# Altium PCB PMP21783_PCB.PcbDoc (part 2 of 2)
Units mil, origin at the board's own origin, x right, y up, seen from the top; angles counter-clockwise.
Board outline 4600 x 4035 mil, 2 copper layers (Top Layer, Bottom Layer), stack 62 mil thick; 142 components, 69 nets, 309 pads, 93 vias.
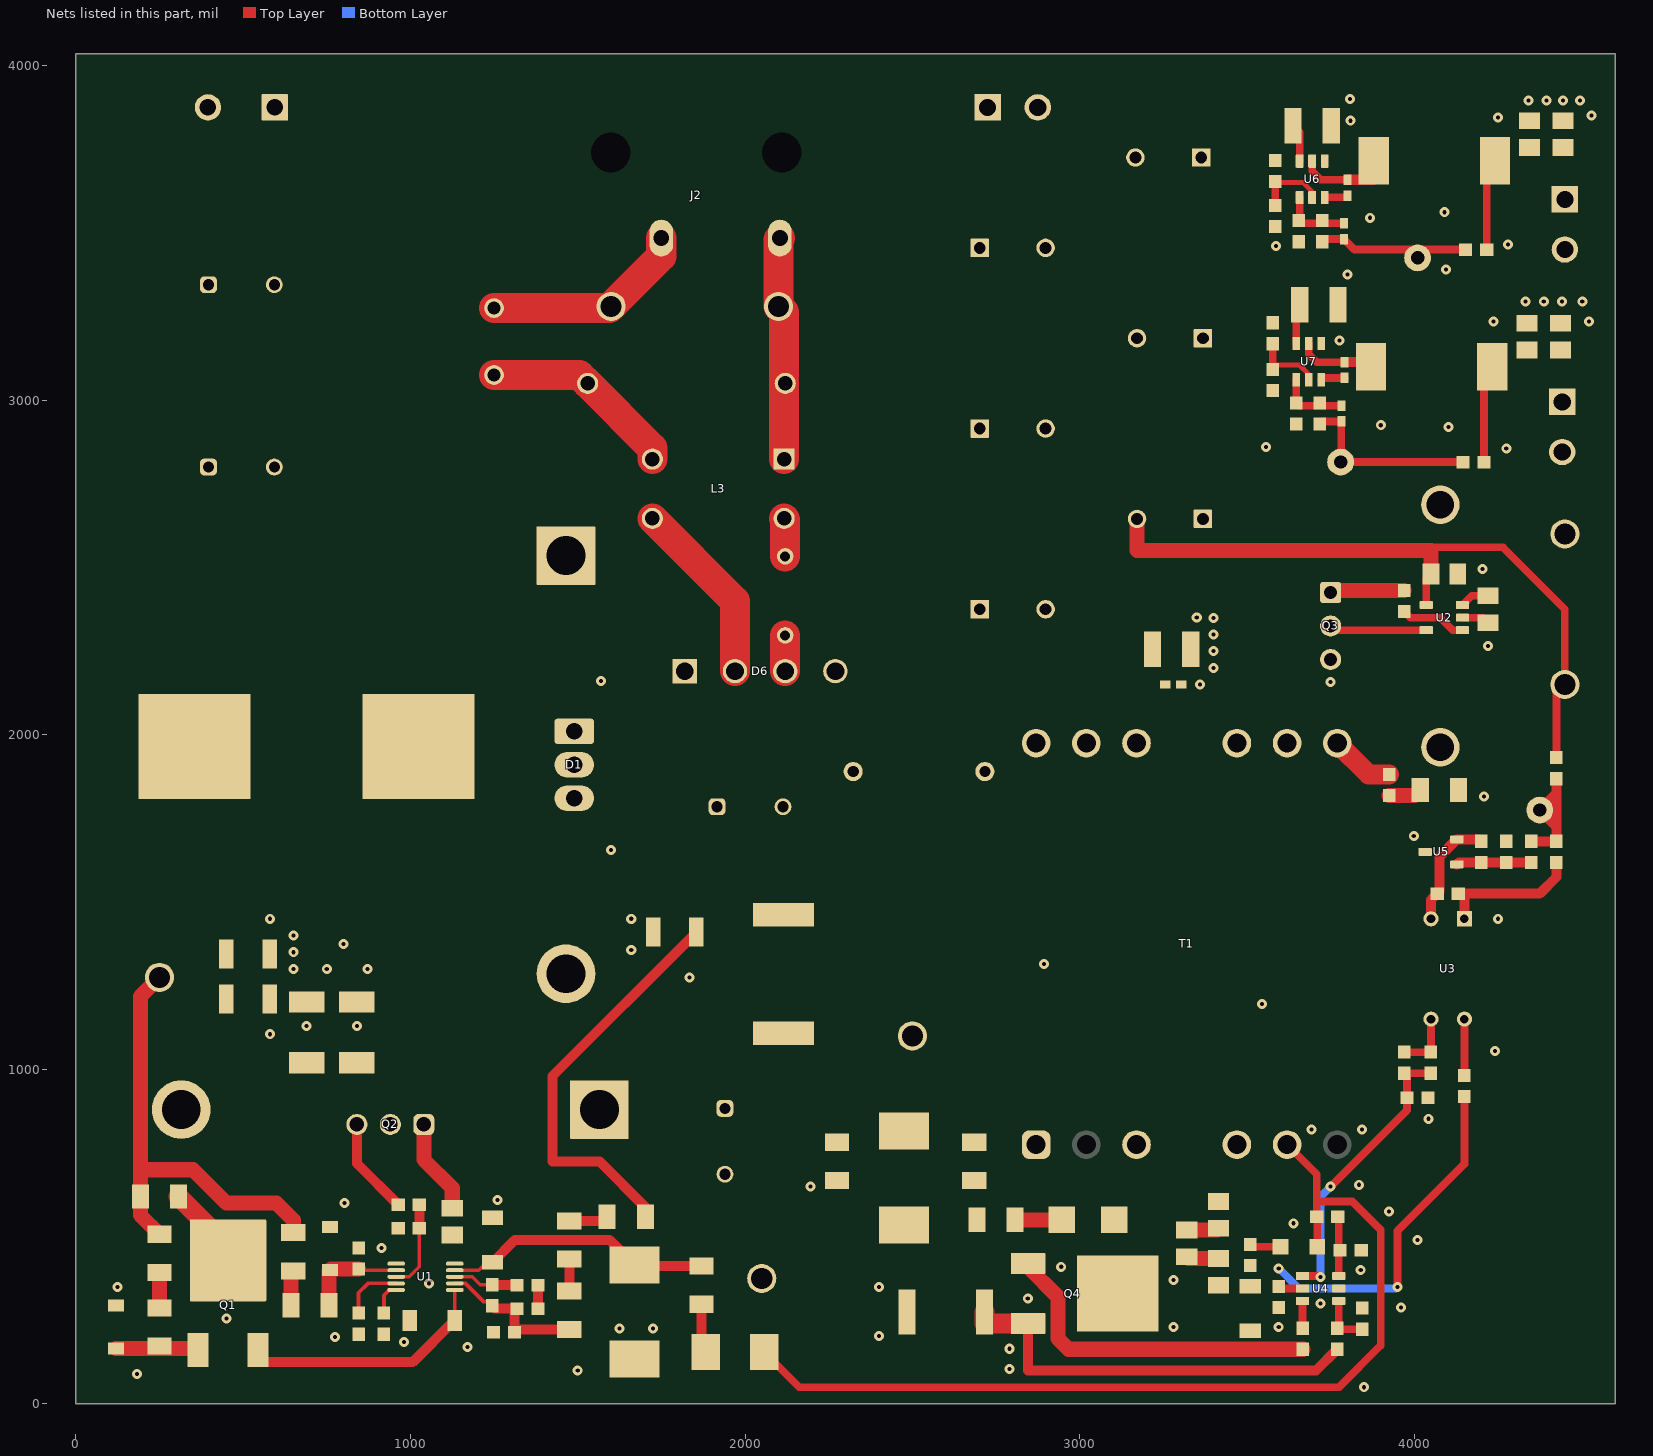
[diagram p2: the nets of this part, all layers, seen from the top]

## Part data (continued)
J3 J4 J5: library part CMP-0054822-2, "Terminal Block, 2x1, 3.81mm, 24-16 AWG, 10A, 300VAC, TH", Manufacturer="Wurth Elektronik"
L1: library part CMP-0085391-1, "Inductor, Shielded, Mn-Zn, 220 µH, 5.3 A, 0.040095 ohm, SMD", Manufacturer="Wurth Elektronik", Value1="0.040095 ohm", Value2=5.3A, ValueDisplayed=220µH
L2: library part CMP-0064437-2, "Inductor, Shielded Drum Core, Ferrite, 22 uH, 1.8 A, 0.11 ohm, SMD", Manufacturer="Wurth Elektronik", Supplier Part Number 1=732-1062-1-ND, Value1="0.11 ohm", Value2=1.8A, ValueDisplayed=22uH
L3: library part CMP-0076875-1, "Coupled inductor, 5 mH, 1.3 A, 0.2 ohm, TH", Manufacturer="Wurth Elektronik", Supplier Part Number 1=732-5576-ND, ValueDisplayed=5mH
L4: library part CMP-0064732-2, "Inductor, Toroid, Powdered Iron, 140 uH, 1 A, 0.11 ohm, TH", Manufacturer="Wurth Elektronik", Value1="0.11 ohm", Value2=1A, ValueDisplayed=140uH
L5 L6: library part CMP-0064006-1, "Inductor, Shielded Drum Core, Ferrite, 10 uH, 8 A, 0.0207 ohm, SMD", Manufacturer="Wurth Elektronik", Supplier Part Number 1=732-2158-1-ND, Value1="0.0207 ohm", Value2=8A, ValueDisplayed=10uH
LN: library part CMP-0055157-1, "Test Point, Multipurpose, Brown, TH", Color=Brown, Manufacturer=Keystone, Supplier Part Number 1=36-5125-ND
Logo1 LOGO6: library part CMP-0074837-1, "IEC 61010-1 Hot Surface Warning"
Logo2 LOGO5: library part CMP-0074835-1, "IEC 61010-1 High Voltage Warning"
Logo3: library part CMP-0074769-1
Logo4: library part CMP-0074847-1, "FCC_disclaimer"
NEU: library part CMP-0055156-1, "Test Point, Multipurpose, Blue, TH", Color=Blue, Manufacturer=Keystone, Supplier Part Number 1=36-5127-ND
Q1: library part CMP-0001119-4, "MOSFET, N-CH, 500 V, 2.8 A, DPAK", Alternate Manufacturer=None, Manufacturer=AOS, Supplier Part Number 1=785-1175-1-ND, Value2="6.7 nC"
Q2: library part CMP-0085354-1, "MOSFET, N-CH, 300 V, 44 A, TO-220-3", Alternate Manufacturer=None, Manufacturer="Infineon Technologies", Value1="? ohm", Value2="65 nC"
Q3: library part CMP-0000955-1, "MOSFET, N-CH, 100 V, 100 A, KCS0003B (TO-220-3)", Alternate Manufacturer=None, Manufacturer="Texas Instruments", Supplier Part Number 1=296-37480-5-ND, Value2="38 nC"
Q4: library part CMP-0081521-2, "MOSFET, N-CH, 700 V, 12.5 A, DPAK", Alternate Manufacturer=None, Manufacturer="Infineon Technologies", Supplier Part Number 1=IPD70R360P7SAUMA1CT-ND, Value1="? ohm", Value2="16.4 nC"
R1 R4: library part CMP-0018610-3, "RES, 1.0 M, 5%, 0.25 W, AEC-Q200 Grade 0, 1206", Manufacturer=Vishay-Dale, Power_W=250mW, Supplier Part Number 1=541-1.0MECT-ND, TempCo="200 ppm/C", Tolerance_%=5%, Value2=0.25W, Value_Code=1M00, ValueDisplayed=1.0M
R2 R5: library part CMP-0018574-3, "RES, 100 k, 5%, 0.25 W, AEC-Q200 Grade 0, 1206", Manufacturer=Vishay-Dale, Power_W=250mW, Supplier Part Number 1=541-100KECT-ND, TempCo="200 ppm/C", Tolerance_%=5%, Value2=0.25W, Value_Code=100k
R3: library part CMP-0016705-3, "RES, 1.54 k, 1%, 0.25 W, AEC-Q200 Grade 0, 1206", Manufacturer=Vishay-Dale, Power_W=250mW, Supplier Part Number 1=541-1.54KFCT-ND, TempCo="100 ppm/C", Tolerance_%=1%, Value2=0.25W, Value_Code=1k54, ValueDisplayed=1.54k
R6: library part CMP-0018242-2, "RES, 390, 1%, 0.25 W, 1206", Manufacturer="Yageo America", Power_W=250mW, Supplier Part Number 1=311-390FRCT-ND, TempCo="100 ppm/C", Tolerance_%=1%, Value2=0.25W, Value_Code=390R, ValueDisplayed=390
R7: library part CMP-0020802-2, "RES, 0, 5%, 0.125 W, 0805", Manufacturer=Rohm, Power_W=125mW, Supplier Part Number 1=RHM0.0ARCT-ND, TempCo="400 ppm/C", Tolerance_%=5%, Value2=0.125W, Value_Code=0000, ValueDisplayed=0
R8: library part CMP-0018328-2, "RES, 49.9, 1%, 0.25 W, 1206", Manufacturer="Yageo America", Power_W=250mW, Supplier Part Number 1=311-49.9FRCT-ND, TempCo="100 ppm/C", Tolerance_%=1%, Value2=0.25W, Value_Code=49R9, ValueDisplayed=49.9
R9 R30: library part CMP-0022109-5, "RES, 1.00 k, 1%, 0.1 W, AEC-Q200 Grade 0, 0603", Manufacturer=Vishay-Dale, Power_W=100mW, Supplier Part Number 1=541-1.00KHCT-ND, TempCo="100 ppm/C", Tolerance_%=1%, Value2=0.1W, Value_Code=1k00, ValueDisplayed=1.00k
R10 R11: library part CMP-0016513-2, "RES, 0.15, 1%, 1 W, 2010", Manufacturer="Stackpole Electronics Inc", Power_W=1W, Supplier Part Number 1=CSR2010FTR150CT-ND, TempCo="100 ppm/C", Tolerance_%=1%, Value_Code=R150, ValueDisplayed=0.15
R12 R15: library part CMP-0017074-3, "RES, 590 k, 1%, 0.25 W, AEC-Q200 Grade 0, 1206", Manufacturer=Vishay-Dale, Power_W=250mW, Supplier Part Number 1=541-590KFCT-ND, TempCo="100 ppm/C", Tolerance_%=1%, Value2=0.25W, Value_Code=590k
R13: library part CMP-0022010-4, "RES, 113 k, 1%, 0.1 W, AEC-Q200 Grade 0, 0603", Manufacturer=Vishay-Dale, Power_W=100mW, Supplier Part Number 1=541-113KHCT-ND, TempCo="100 ppm/C", Tolerance_%=1%, Value2=0.1W, Value_Code=113k
R14: library part CMP-0022628-4, "RES, 86.6 k, 1%, 0.1 W, AEC-Q200 Grade 0, 0603", Manufacturer=Vishay-Dale, Power_W=100mW, Supplier Part Number 1=541-86.6KHCT-ND, TempCo="100 ppm/C", Tolerance_%=1%, Value2=0.1W, Value_Code=86k6, ValueDisplayed=86.6k
R16: library part CMP-0021998-4, "RES, 10.0 k, 1%, 0.1 W, AEC-Q200 Grade 0, 0603", Manufacturer=Vishay-Dale, Power_W=100mW, Supplier Part Number 1=541-10.0KHCT-ND, TempCo="100 ppm/C", Tolerance_%=1%, Value2=0.1W, Value_Code=10k0, ValueDisplayed=10.0k
R17: library part CMP-0022204-4, "RES, 20.0 k, 1%, 0.1 W, AEC-Q200 Grade 0, 0603", Manufacturer=Vishay-Dale, Power_W=100mW, Supplier Part Number 1=541-20.0KHCT-ND, TempCo="100 ppm/C", Tolerance_%=1%, Value2=0.1W, Value_Code=20k0, ValueDisplayed=20.0k
R18 R19 R22: library part CMP-0021616-2, "RES, 2.00 M, 1%, 0.125 W, AEC-Q200 Grade 0, 0805", Manufacturer=Panasonic, Power_W=125mW, Supplier Part Number 1=P2.00MCCT-ND, TempCo="100 ppm/C", Tolerance_%=1%, Value2=0.125W, Value_Code=2M00, ValueDisplayed=2.00M
R20 R24: library part CMP-0018573-3, "RES, 0, 5%, 0.25 W, AEC-Q200 Grade 0, 1206", Manufacturer=Vishay-Dale, Power_W=250mW, Supplier Part Number 1=541-0.0ECT-ND, TempCo="200 ppm/C", Tolerance_%=5%, Value2=0.25W, Value_Code=0000, ValueDisplayed=0
R21 R27 R29: library part CMP-0025697-4, "RES, 0, 5%, 0.1 W, AEC-Q200 Grade 0, 0603", Manufacturer=Vishay-Dale, Power_W=100mW, Supplier Part Number 1=541-0.0GCT-ND, TempCo="200 ppm/C", Tolerance_%=5%, Value2=0.1W, Value_Code=0000, ValueDisplayed=0
R23 R42 R43: library part CMP-0022448-4, "RES, 49.9, 1%, 0.1 W, AEC-Q200 Grade 0, 0603", Manufacturer=Vishay-Dale, Power_W=100mW, Supplier Part Number 1=541-49.9HCT-ND, TempCo="100 ppm/C", Tolerance_%=1%, Value2=0.1W, Value_Code=49R9, ValueDisplayed=49.9
R25: library part CMP-0025743-4, "RES, 1.0, 5%, 0.1 W, AEC-Q200 Grade 0, 0603", Manufacturer=Vishay-Dale, Power_W=100mW, Supplier Part Number 1=541-1.0GCT-ND, TempCo="200 ppm/C", Tolerance_%=5%, Value2=0.1W, Value_Code=1R00, ValueDisplayed=1.0
R26: library part CMP-0022269-4, "RES, 2.05 k, 1%, 0.1 W, AEC-Q200 Grade 0, 0603", Manufacturer=Vishay-Dale, Power_W=100mW, Supplier Part Number 1=541-2.05KHCT-ND, TempCo="100 ppm/C", Tolerance_%=1%, Value2=0.1W, Value_Code=2k05, ValueDisplayed=2.05k
R28: library part CMP-0022659-4, "RES, 95.3 k, 1%, 0.1 W, AEC-Q200 Grade 0, 0603", Manufacturer=Vishay-Dale, Power_W=100mW, Supplier Part Number 1=541-95.3KHCT-ND, TempCo="100 ppm/C", Tolerance_%=1%, Value2=0.1W, Value_Code=95k3, ValueDisplayed=95.3k
R31: library part CMP-0021996-4, "RES, 107 k, 1%, 0.1 W, AEC-Q200 Grade 0, 0603", Manufacturer=Vishay-Dale, Power_W=100mW, Supplier Part Number 1=541-107KHCT-ND, TempCo="100 ppm/C", Tolerance_%=1%, Value2=0.1W, Value_Code=107k
R32: library part CMP-0022334-4, "RES, 32.4 k, 1%, 0.1 W, AEC-Q200 Grade 0, 0603", Manufacturer=Vishay-Dale, Power_W=100mW, Supplier Part Number 1=541-32.4KHCT-ND, TempCo="100 ppm/C", Tolerance_%=1%, Value2=0.1W, Value_Code=32k4, ValueDisplayed=32.4k
R33: library part CMP-0022125-4, "RES, 1.47 k, 1%, 0.1 W, AEC-Q200 Grade 0, 0603", Manufacturer=Vishay-Dale, Power_W=100mW, Supplier Part Number 1=541-1.47KHCT-ND, TempCo="100 ppm/C", Tolerance_%=1%, Value2=0.1W, Value_Code=1k47, ValueDisplayed=1.47k
R34 R47: library part CMP-0022220-4, "RES, 22.1 k, 1%, 0.1 W, AEC-Q200 Grade 0, 0603", Manufacturer=Vishay-Dale, Power_W=100mW, Supplier Part Number 1=541-22.1KHCT-ND, TempCo="100 ppm/C", Tolerance_%=1%, Value2=0.1W, Value_Code=22k1, ValueDisplayed=22.1k
R35: library part CMP-0015783-2, "RES, 0.25, 1%, 2 W, 2512", Manufacturer="Stackpole Electronics Inc", Power_W=2W, Supplier Part Number 1=CSRN2512FKR250CT-ND, TempCo="200 ppm/C", Tolerance_%=1%, Value_Code=R250, ValueDisplayed=0.25
R36: library part CMP-0022449-4, "RES, 4.02 k, 1%, 0.1 W, AEC-Q200 Grade 0, 0603", Manufacturer=Vishay-Dale, Power_W=100mW, Supplier Part Number 1=541-4.02KHCT-ND, TempCo="100 ppm/C", Tolerance_%=1%, Value2=0.1W, Value_Code=4k02, ValueDisplayed=4.02k
R37: library part CMP-0022016-4, "RES, 11.0 k, 1%, 0.1 W, AEC-Q200 Grade 0, 0603", Manufacturer=Vishay-Dale, Power_W=100mW, Supplier Part Number 1=541-11.0KHCT-ND, TempCo="100 ppm/C", Tolerance_%=1%, Value2=0.1W, Value_Code=11k0, ValueDisplayed=11.0k
R38 R39: library part CMP-0022480-4, "RES, 511 k, 1%, 0.1 W, AEC-Q200 Grade 0, 0603", Manufacturer=Vishay-Dale, Power_W=100mW, Supplier Part Number 1=541-511KHCT-ND, TempCo="100 ppm/C", Tolerance_%=1%, Value2=0.1W, Value_Code=511k
R40 R41: library part CMP-0021994-4, "RES, 105 k, 1%, 0.1 W, AEC-Q200 Grade 0, 0603", Manufacturer=Vishay-Dale, Power_W=100mW, Supplier Part Number 1=541-105KHCT-ND, TempCo="100 ppm/C", Tolerance_%=1%, Value2=0.1W, Value_Code=105k
R44 R45: library part CMP-0021990-4, "RES, 100 k, 1%, 0.1 W, AEC-Q200 Grade 0, 0603", Manufacturer=Vishay-Dale, Power_W=100mW, Supplier Part Number 1=541-100KHCT-ND, TempCo="100 ppm/C", Tolerance_%=1%, Value2=0.1W, Value_Code=100k
R46: library part CMP-0022043-4, "RES, 13.3 k, 1%, 0.1 W, AEC-Q200 Grade 0, 0603", Manufacturer=Vishay-Dale, Power_W=100mW, Supplier Part Number 1=541-13.3KHCT-ND, TempCo="100 ppm/C", Tolerance_%=1%, Value2=0.1W, Value_Code=13k3, ValueDisplayed=13.3k
T1: library part CMP-0085998-1, "Transformer, 150 uH, TH", Manufacturer="Renco Electronics", ValueDisplayed=150µH
TP1 TP2 TP3: library part CMP-0055147-1, "Test Point, Multipurpose, Red, TH", Color=Red, Manufacturer=Keystone, Supplier Part Number 1=36-5010-ND
TP4 TP7 TP8: library part CMP-0055139-1, "Test Point, Miniature, White, TH", Color=White, Manufacturer=Keystone, Supplier Part Number 1=36-5002-ND
TP5 TP6: library part CMP-0055148-1, "Test Point, Multipurpose, Black, TH", Color=Black, Manufacturer=Keystone, Supplier Part Number 1=36-5011-ND
U1: library part CMP-0073090-1, "60V Low Side Controller for Boost and SEPIC, 10-pin MSOP", Manufacturer="Texas Instruments", PackageTopMarking=ZXTT*5022, PowerWise=Y
U2: library part CMP-0013050-3, "High-Frequency Multi-Mode Synchronous Rectifier Controller, DBV0005A (SOT-23-5)", Alternate Manufacturer="Texas Instruments", Alternate PartNumber=UCC24612-1DBVT
U3: library part CMP-0006187-3, "Optocoupler, 5.3 kV, 50-600% CTR, TH", Manufacturer=Vishay-Semiconductor, Supplier Part Number 1=VO618A-ND-3, Voltage_Isolation_Vrms=5.3kV
U4: library part CMP-0078369-2, "High-Efficiency Low-Cost Flyback Controller with Secondary-Side Regulation, DBV0006A (SOT-23-6)", Alternate Manufacturer="Texas Instruments"
U5: library part CMP-0033139-1, "Low-Voltage Adjustable Precision Shunt Regulator, 80 mA, -40 to 125 degC, 3-pin SOT-23 (DBZ), Green (RoHS & no Sb/Br)", Manufacturer="Texas Instruments", Rating=Catalog, Temp Coeff(Max)(ppm/ degree C)=129
U6 U7: library part CMP-0073977-2, "4.5-V to 28-V Input, 3-A Output, EMI Friendly Synchronous Step-Down Converter, DDC0006A (SOT-23-T-6)", Alternate Manufacturer="Texas Instruments", Alternate PartNumber=TPS54302DDCT

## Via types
v1: diameter 29.92, hole 12.2, Top Layer to Bottom Layer, 89 vias
v2: diameter 29.92, hole 12.2, Top Layer to Bottom Layer, tented both sides, 4 vias

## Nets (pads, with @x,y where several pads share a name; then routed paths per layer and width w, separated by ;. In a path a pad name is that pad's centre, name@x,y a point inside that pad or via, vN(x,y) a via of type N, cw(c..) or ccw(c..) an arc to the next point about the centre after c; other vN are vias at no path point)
12V: C14.2 C15.2 C16.2 C17.2 C18.2 C19.2 C20.1 C21.1 C27.1 C36.1 C37.1 J3.2 R23.2 R38.2 R39.2 T1.10 T1.11 T1.12 TP2.1 U2.4 U6.3 U7.3 | length 2306.8
  Top Layer w23: C36.1@3637.91,3820 3657.6,3800.31 U6.3@3657.6,3714.13 ; U7.3@3647.25,3169.04 3647.25,3274.33 C37.1@3657.91,3285 ; U2.4@4035.87,2387.4 4035.87,2465.87 C27.1@4050,2480 ; 4050,2560 4265,2560 4450,2375 TP2.1@4450,2150 4425,2125 R23.2@4425,1931.5
  Top Layer w45: C19.2@3171.57,2645 3171.57,2550 4050,2550 C27.1@4050,2480
AUX: D2.2 D9.2 R31.2 T1.5 | length 2852.3
  Top Layer w23: D2.2@2057.01,155 2162.01,50 3775,50 3900,175 3900,520 3815,605 3708.51,605 ; T1.5@3620,775 3708.51,686.5 3708.51,605 ; D9.2@3710.12,470 3710.12,558.39 R31.2@3708.51,560 3708.51,605
FB_U1: C11.1 C12.1 R15.1 R16.2 U1.2 | length 456.8
  Top Layer w11: U1.2@1132.6,360.31 1164.69,360.31 1220,305 1233.5,305 C11.1@1245,293.5
  Top Layer w30: C11.1@1245,293.5 1253.5,285 C12.1@1318.5,285 1311.5,277.99 R16.2@1311.5,215 1319.41,222.91 R15.1@1475,222.91
FB_U4: C30.2 R32.1 R36.2 U4.1 | length 854.2
  Top Layer w23: U4.1@3665.87,382.4 3717.6,382.4 v1(3720,380) ; v1(3750,650) 3978.5,878.51 R36.2@3978.5,915 3978.5,980 C30.2@3970,988.5 R32.1@4050,988.5
  Bottom Layer w23: v1(3720,380) 3720,620 v1(3750,650)
FB_U6: C42.2 R44.1 R46.2 U6.4 | length 208.7
  Top Layer w23: U6.4@3657.6,3605.86 3657.6,3539.09 R46.2@3655,3536.49 3662.87,3528.62 C42.2@3790,3528.62
FB_U7: C43.2 R45.1 R47.2 U7.4 | length 207.7
  Top Layer w23: U7.4@3647.25,3060.78 3647.25,2991.53 R47.2@3647.12,2991.41 3655,2983.53 C43.2@3782.12,2983.53
GND: C1.2 C2.2 C3.2 C4.2 C5.2 C6.2 C7.2 C8.2 C9.2 C10.2 C22.2 C23.2 C28.2 C29.1 C32.2 C33.2 D3.2 D4.2 D5.2 D6.4 H1.1 H1.2 H2.1 H2.2 J1.1 R10.1 R11.1 R13.1 R14.1 R16.1 R34.1 R35.1 R36.1 T1.4 TP5.1 U1.6 U4.5
  other v1: 3850,50 183.07,89.53 1500,100 2790,105 2790,165 1170,170 981.08,185 775,200 2400,202.89 1625,225 1725,225 3280,230 3595,230 450,255 3960,288.33 2845,315 125,350 2400,350 1055,360 3280,370 3840,400 2945,410 914.03,466.5 4009.19,490 3639.12,540 3925,575 802.5,600.31 1260,610 2195.91,650 3835,655 3692.48,820.16 3843.5,820.16 4042,852.3 4241.1,1055 580,1105 690,1130 840,1130 3545,1195 1834.57,1275 650,1300 750,1300 872.27,1300 2894,1315 650,1350 1660,1357.27 800,1375 650,1400 580,1450 1660,1450 1600,1655 1569.54,2160
  other v2: 3720,300
NetC1_1: C1.1 C2.1 C3.1 C4.1 J1.2 L1.1 R1.1 R2.2 R3.2 TP1.1 | length 1372.3
  Top Layer w45: R2.2@250,507.09 192.91,564.17 R3.2@192.91,620 192.91,700 ; TP1.1@250,1275 192.91,1217.91 192.91,700 ; R1.1@650,512.09 650,550 600,600 450,600 350,700 192.91,700
NetC5_1: C5.1 C6.1 D1.2 D6.1 L2.1 R8.2 | length 1224.9
  Top Layer w30: R8.2@1702.09,560 1702.09,587.91 1565,725 1425,725 1425,980.04 C6.1@1854.96,1410
NetC7_1: C7.1 Q1.3 U1.1 | length 766
  Top Layer w11: C7.1@1131.93,250 1132.6,250.67 U1.1@1132.6,340.63
  Top Layer w30: Q1.3@544.76,161.14 544.76,125 1006.93,125 C7.1@1131.93,250
NetC8_1: C8.1 D3.1 R6.2 U1.4 | length 807.1
  Top Layer w11: U1.4@1132.6,399.68 1204.19,399.68 1227.58,423.07 C8.1@1245,423.07
  Top Layer w30: C8.1@1245,423.07 1311.93,490 1595.49,490 D3.1@1670,415.49 1673.41,412.09 R6.2@1870,412.09
NetC9_1: C9.1 R9.1 U1.8 | length 266.5
  Top Layer w11: U1.8@957.4,380 996.5,380 1026.5,410 C9.1@1026.5,525
  Top Layer w30: C9.1@1026.5,525 R9.1@1026.5,595
NetC10_1: C10.1 U1.10 | length 96.8
  Top Layer w11: C10.1@920,271.5 920.98,272.48 920.98,325 936.61,340.63 U1.10@957.4,340.63
NetC11_2: C11.2 R17.1 U1.3 | length 196.3
  Top Layer w11: U1.3@1132.6,380 1185,380 1208.5,356.5 C11.2@1245,356.5
  Top Layer w30: C11.2@1245,356.5 1246.5,355 R17.1@1318.5,355
NetC12_2: C12.2 R17.2 | length 70
  Top Layer w30: C12.2@1381.5,285 R17.2@1381.5,355
NetC13_1: C13.1 F1.1 L3.2 | length 596.6
  Top Layer w90: F1.1@1250,3075 1504.72,3075 C13.1@1529.72,3050 1723.15,2856.57 L3.2@1723.15,2823.58
NetC13_2: C13.2 J2.1 L3.1 NEU.1 | length 669.2
  Top Layer w90: J2.1@2104.09,3484.09 2100,3480 NEU.1@2100,3280 2116.85,3263.15 L3.1@2116.85,2823.58
NetC24_2: C24.2 D7.1 R20.2
NetC25_1: C25.1 R24.2 | length 99.7
  Top Layer w45: C25.1@3925,1818.5 4001.42,1818.5 R24.2@4017.91,1835
NetC25_2: C25.2 Q3.2 T1.7 T1.8 T1.9 U2.5 | length 484.7
  Top Layer w23: Q3.2@3750,2325 3762.4,2312.6 U2.5@4035.87,2312.6
  Top Layer w60: T1.7@3770,1975 3863.51,1881.5 C25.2@3925,1881.5
NetC26_1: C26.1 U2.3 | length 87.3
  Top Layer w23: U2.3@4144.13,2387.4 4171.74,2415 C26.1@4220,2415
NetC28_1: C28.1 C29.2 R22.1 R25.2 R27.2 U4.2 | length 1106.8
  Top Layer w23: C29.2@3595,351.5 3601.5,345 U4.2@3665.87,345 ; v1(3950,350) 3950,517.09 4150,717.09 R27.2@4150,918.5
  Bottom Layer w23: v2(3595,405) 3655.01,345 3945,345 v1(3950,350)
NetC30_1: C30.1 R32.2 U3.3 | length 178.5
  Top Layer w23: C30.1@3970,1051.5 R32.2@4050,1051.5 U3.3@4050,1150
NetC31_1: C31.1 R28.1 R37.2 U5.1 | length 225.2
  Top Layer w30: U5.1@4127.24,1612.6 4133.15,1618.5 C31.1@4200,1618.5 R28.1@4350,1618.5
NetC31_2: C31.2 R30.1 U3.2 U5.2 | length 344.6
  Top Layer w30: U3.2@4050,1450 4050,1506.5 R30.1@4068.5,1525 4075.31,1531.81 4075.31,1635.47 U5.2@4127.24,1687.4 4194.09,1687.4 C31.2@4200,1681.5
NetC32_1: C32.1 R33.1 U4.4 | length 150.8
  Top Layer w23: U4.4@3774.14,307.6 3774.14,230.63 3781.26,223.51 C32.1@3845,223.51
NetC34_1: C34.1 U6.6 | length 69.9
  Top Layer w23: U6.6@3732.4,3605.86 3794.49,3605.86 C34.1@3800,3611.38
NetC34_2: C34.2 L5.1 U6.2 | length 281.1
  Top Layer w23: U6.2@3695,3714.13 3695,3683.62 3720,3658.62 C34.2@3800,3658.62
  Top Layer w30: C34.2@3800,3658.62 3878.89,3658.62 L5.1@3878.89,3715
NetC35_1: C35.1 U7.6 | length 72.4
  Top Layer w23: U7.6@3722.05,3060.78 3727.56,3066.29 C35.1@3792.12,3066.29
NetC35_2: C35.2 L6.1 U7.2 | length 233.6
  Top Layer w23: U7.2@3684.65,3169.04 3684.65,3137.39 3708.5,3113.53 C35.2@3792.12,3113.53
  Top Layer w30: C35.2@3792.12,3113.53 3857.4,3113.53 L6.1@3871.02,3099.91
NetC38_1: C38.1 C39.1 J4.1 L5.2 R42.2 | length 275.2
  Top Layer w23: R42.2@4216.49,3450 4216.49,3690.39 L5.2@4241.1,3715
NetC40_1: C40.1 C41.1 J5.1 L6.2 R43.2 | length 295.2
  Top Layer w23: R43.2@4208.62,2814.91 4208.62,3075.3 L6.2@4233.22,3099.91
NetC42_1: C42.1 R42.1 R44.2 TP7.1 | length 444.8
  Top Layer w23: R44.2@3725,3473.5 3732.87,3481.38 C42.1@3790,3481.38 3821.38,3450 R42.1@4153.5,3450
NetC43_1: C43.1 R43.1 R45.2 TP8.1 | length 531.9
  Top Layer w23: R45.2@3717.12,2928.41 3725,2936.29 C43.1@3782.12,2936.29 3782.12,2851.2 3818.41,2814.91 R43.1@4145.63,2814.91
NetD1_1: D1.1 D1.3 L1.2 Q2.2
NetD2_1: D2.1 R6.1 | length 148.3
  Top Layer w30: R6.1@1870,297.91 1870,167.99 D2.1@1882.99,155
NetD4_1: D4.1 Q1.1 R5.1 | length 247.1
  Top Layer w45: D4.1@120,165.53 360.85,165.53 Q1.1@365.24,161.14
NetD5_1: D5.1 R4.2 R13.2 U1.7 | length 307
  Top Layer w11: R13.2@845,403.5 848.82,399.68 U1.7@957.4,399.68
  Top Layer w45: R4.2@757.09,295 757.09,397.62 D5.1@760,400.53 762.97,403.5 R13.2@845,403.5
NetD6_2: D6.2 L3.3 | length 558.7
  Top Layer w90: L3.3@1723.15,2646.42 1970,2399.56 D6.2@1970,2190
NetD6_3: D6.3 L4.2 | length 106.9
  Top Layer w90: D6.3@2120,2190 L4.2@2120,2296.89
NetD8_1: D8.1 R20.1 | length 139.2
  Top Layer w45: R20.1@2807.09,550 D8.1@2946.26,550
NetD8_2: D8.2 Q4.2 T1.3
NetD9_1: D9.1 R25.1 | length 80.5
  Top Layer w23: R25.1@3520,471.5 3521.5,470 D9.1@3599.89,470
NetF1_2: F1.2 J2.2 LN.1 | length 618.2
  Top Layer w90: F1.2@1250,3275 1595,3275 LN.1@1600,3280 1749.76,3429.76 1749.76,3483.6 J2.2@1749.76,3484.09
NetL3_4: L3.4 L4.1 | length 114.6
  Top Layer w90: L3.4@2116.85,2646.42 2120,2643.26 L4.1@2120,2533.11
NetQ1_2: Q1.2 R3.1 | length 252.4
  Top Layer w60: R3.1@307.09,620 455,472.09 Q1.2@455,428.86
NetQ2_1: Q2.1 R7.2 | length 285.5
  Top Layer w45: Q2.1@1040,835.32 1040,730 1125,645 R7.2@1125,585
NetQ2_3: Q2.3 R9.2 R10.2 R11.2 | length 291.5
  Top Layer w30: Q2.3@840,835.32 840,718.5 R9.2@963.5,595
NetQ3_1: Q3.1 R21.2 | length 222.7
  Top Layer w45: Q3.1@3750,2425 3756.5,2431.5 R21.2@3970,2431.5
NetQ4_1: Q4.1 R29.2 | length 1006.7
  Top Layer w45: Q4.1@2846.14,419.77 2846.14,408.86 2935,320 2935,195 2966.49,163.51 R29.2@3667.09,163.51
NetQ4_3: Q4.3 R33.2 R35.2 | length 1255.2
  Top Layer w30: Q4.3@2846.14,240.24 2846.14,100 3706.5,100 R33.2@3770,163.51
  Top Layer w60: R35.2@2716.14,275 2716.14,240.24 Q4.3@2846.14,240.24
NetR1_2: R1.2 R4.1 | length 105.8
  Top Layer w45: R4.1@642.91,295 642.91,390.83 R1.2@650,397.91
NetR2_1: R2.1 R5.2 | length 105.8
  Top Layer w45: R5.2@250,287.09 R2.1@250,392.91
NetR7_1: R7.1 U1.5
NetR8_1: R8.1 R12.2 | length 118.3
  Top Layer w30: R12.2@1475,547.09 1575,547.09 R8.1@1587.91,560
NetR12_1: R12.1 R15.2 | length 95.8
  Top Layer w30: R15.2@1475,337.09 R12.1@1475,432.91
NetR14_2: R14.2 U1.9 | length 184.7
  Top Layer w11: R14.2@845,271.5 845,332.09 873.23,360.31 U1.9@957.4,360.31
NetR18_1: R18.1 R19.2 | length 97.1
  Top Layer w45: R19.2@3320,520 3410,520 R18.1@3415,525
NetR19_1: R19.1 R22.2 | length 97.1
  Top Layer w45: R19.1@3320,440 3325,435 R22.2@3415,435
NetR21_1: R21.1 U2.1 | length 197.3
  Top Layer w23: R21.1@3970,2368.5 3988.5,2350 4078.23,2350 4115.63,2312.6 U2.1@4144.13,2312.6
NetR23_1: R23.1 R26.2 R28.2 TP4.1 | length 403.4
  Top Layer w30: R28.2@4350,1681.5 R26.2@4425,1681.5 4425,1725 ; R23.1@4425,1868.5 4425,1825 ; 4425,1725 4425,1825 ; 4425,1725 TP4.1@4375,1775 4425,1825
NetR26_1: R26.1 R30.2 U3.1 | length 432.7
  Top Layer w30: R30.2@4131.5,1525 R30.2@4150,1525 ; U3.1@4150,1450 R30.2@4150,1525 ; R26.1@4425,1618.5 4425,1575 4375,1525 R30.2@4150,1525
NetR27_1: R27.1 U3.4 | length 168.5
  Top Layer w23: R27.1@4150,981.5 U3.4@4150,1150
NetR29_1: R29.1 U4.3 | length 81.6
  Top Layer w23: U4.3@3665.87,307.6 3665.87,227.72 R29.1@3667.09,226.5
NetR31_1: R31.1 R34.2 U4.6 | length 178.7
  Top Layer w23: R31.1@3771.5,560 3774.14,557.36 U4.6@3774.14,382.4
NetR38_1: R38.1 R40.2 U6.5 | length 211.7
  Top Layer w15: R38.1@3585,3653.5 3587.52,3650.98 3666.85,3650.98 3695,3622.84 U6.5@3695,3605.86
  Top Layer w23: R40.2@3585,3581.49 R38.1@3585,3653.5
NetR39_1: R39.1 R41.2 U7.5 | length 218.1
  Top Layer w15: R41.2@3577.12,3091.41 3590.63,3104.91 3657.12,3104.91 3684.65,3077.39 U7.5@3684.65,3060.78
  Top Layer w23: R41.2@3577.12,3091.41 R39.1@3577.12,3168.41
RTN: C14.1 C15.1 C16.1 C17.1 C18.1 C19.1 C20.2 C21.2 C26.2 C27.2 C33.1 C36.2 C37.2 C38.2 C39.2 C40.2 C41.2 H3.1 H3.2 J3.1 J4.2 J5.2 Q3.3 R24.1 R37.1 R40.1 R41.1 R46.1 R47.1 TP6.1 U2.2 U5.3 U6.1 U7.1 | length 82.1
  Top Layer w23: U2.2@4144.13,2350 4205,2350 C26.2@4220,2335
  other v1: 4250,1450 3998.54,1697.21 4208.62,1816 3360,2150 3750,2157.8 3400,2200 3400,2250 4220,2265.37 3400,2300 3400,2349.41 3350,2350 4203.7,2495 4275,2855 3556.45,2860 4102.97,2920 3900,2925 4237.12,3234.91 4522.12,3234.91 4332.12,3294.6 4387.12,3294.91 4442.12,3294.91 4502.12,3294.91 3800,3375 4095,3390 3587.09,3460 4280,3465 3867.71,3545 4090,3561.5 4250,3845 4530,3850 4341.73,3895 4395,3895 4445,3895 4495,3895 3808.04,3900
  other v2: 3777.12,3178.26 3810,3835
VBULK: C22.1 C23.1 C24.1 D7.2 L2.2 R18.2 T1.1 TP3.1
pads on no net: J2.MH1 J2.MH2 T1.2 T1.6

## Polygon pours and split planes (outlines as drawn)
RTN on Top Layer "TOP_LAYER_RTN_P042" (solid, remove dead copper, pour order 42): 4600,4035 4600,1375 4025,1375 3600,1800 2725,1800 2650,1875 2650,2250 2500,2400 2500,4035
12V on Top Layer "TOP_LAYER_12V_P040" (solid, remove dead copper, pour order 40): 3275,1925 2800,1925 2800,3925 3670,3925 3670,3685 3515,3685 3400,3800 3300,3800 3300,3500 3450,3350 3685,3350 3685,3150 3560,3150 3560,3198.33 3508.33,3250 3325,3250 3275,3200
NetC25_2 on Top Layer "TOP_LAYER_NETC25_2_P036" (solid, remove dead copper, pour order 36): 3785,2365 3640,2365 3425,2150 3425,1930 3815,1930 3815,2005.67 3682.5,2138.16 3682.5,2265.37 3707.13,2290 3785,2290
GND on Top Layer "TOP_LAYER_GND_P030" (solid, remove dead copper, pour order 30): 0,4000 850,4000 850,3050 1275,2625 1555,2625 1555,2435 1890,2100 2230,2100 2230,2230 2286.81,2230 2375,2141.81 2375,1750 2675,1450 3400,1450 3625,1225 4300,1225 4300,0 0,0
NetC40_1 on Top Layer "TOP_LAYER_NETC40_1_P026" (solid, remove dead copper, pour order 26): 4602.12,3184.91 4152.12,3184.91 4152.12,2914.91 4602.12,2914.91
NetC38_1 on Top Layer "TOP_LAYER_NETC38_1_P024" (solid, remove dead copper, pour order 24): 4610,3800 4160,3800 4160,3525 4610,3525
NetC28_1 on Top Layer "TOP_LAYER_NETC28_1_P016" (solid, remove dead copper, pour order 16): 3380,320 3380,385 3455,385 3505,435 3615,435 3615,320
NetD8_2 on Top Layer "TOP_LAYER_NETD8_2_P014" (solid, remove dead copper, pour order 14): 3250,850 3250,400.53 3050,400.53 3050,525 3050,850
NetC24_2 on Top Layer "TOP_LAYER_NETC24_2_P012" (solid, remove dead copper, pour order 12): 2750,720 2750,475 2395,475 2395,720
VBULK on Top Layer "TOP_LAYER_VBULK_P010" (solid, remove dead copper, pour order 10): 1900,1175 3450,1175 3450,575 3250,575 3250,850 3080,850 2950,720 1900,720
NetQ2_3 on Top Layer "TOP_LAYER_NETQ2_3_P008" (solid, remove dead copper, pour order 8): 950,1065 627.01,1065 627.01,972.99 830,770 875,770 875,925 950,1000
NetD1_1 on Top Layer "TOP_LAYER_NETD1_1_P006" (solid, remove dead copper, pour order 6): 895,800 1000,800 1200,1000 1200,1425 1550,1775 1550,2059.72 1459.72,2150 850,2150 850,1400 950,1300 950,1000 895,945
NetC5_1 on Top Layer "TOP_LAYER_NETC5_1_P004" (solid, remove dead copper, pour order 4): 1865,2235 1755,2235 1470,1950 1425,1950 1425,1870 1485,1870 1800,1555 1800,1350 2250,1350 2250,1500 2000,1750 2000,2100 1920,2100 1865,2155
NetC1_1 on Top Layer "TOP_LAYER_NETC1_1_P002" (solid, remove dead copper, pour order 2): 500,1150 0,1150 0,4000 500,4000
NetC1_1 on Top Layer "TOP_LAYER_NETC1_1_P000" (solid, remove dead copper, pour order 0): 0,4000
RTN on Bottom Layer "BOTTOM_LAYER_RTN_P044" (solid, remove dead copper, pour order 44): 4600,4035 4600,1375 4025,1375 3600,1800 2725,1800 2650,1875 2650,2250 2500,2400 2500,4035
GND on Bottom Layer "BOTTOM_LAYER_GND_P034" (solid, remove dead copper, pour order 34): 0,4000 850,4000 850,3050 1275,2625 1555,2625 1555,2435 1890,2100 2125,2100 2255,2230 2286.81,2230 2375,2141.81 2375,1750 2675,1450 3400,1450 3625,1225 4300,1225 4300,0 0,0

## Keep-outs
Keep-Out Layer:
  text ".Layer_Name" at 577,-858.49 h60

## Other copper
Top Layer:
  region net GND: 990,481 920,481 920,415 990,415
  region net NetR7_1: 1160,529.47 1090.53,529.47 1090,530 1090,415 1160,415
  text ".Layer_Name" at 577,-858.49 h60
Bottom Layer:
  text ".Layer_Name" at 577,-858.49 h60

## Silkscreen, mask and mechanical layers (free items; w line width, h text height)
Top Overlay:
  lines w10: 1085,85 1085,140 1155,140 1155,85 1085,85 ; 3484.57,85 3554.57,85 3554.57,140 3484.57,140 3484.57,85 ; 3509.57,2895 3509.57,2950 3579.57,2950 3579.57,2895 3509.57,2895 ; 3533.15,3910 3533.15,3965 3603.15,3965 3603.15,3910 3533.15,3910 ; 3910.02,1610 3910.02,1680 3965.02,1680 3965.02,1610 3910.02,1610 ; 4090,2169.56 4090,2239.56 4145,2239.56 4145,2169.56 4090,2169.56
  text "'.PRJ_Number'.PCB_Rev" at 4400,122.92 h108.27 r90
  text ".Layer_Name" at 577,-858.49 h60
Bottom Overlay:
  text ".Layer_Name" at 577,-858.49 h60
Top Paste:
  text ".Layer_Name" at 577,-858.49 h60
Bottom Paste:
  text ".Layer_Name" at 577,-858.49 h60
Top Solder:
  text ".Layer_Name" at 577,-858.49 h60
  text ".Layer_Name" at 577,-858.49 h60
Bottom Solder:
  text ".Layer_Name" at 577,-858.49 h60
Drill Guide:
  text ".Layer_Name" at 577,-858.49 h60
M1 Board Outline:
  the board outline again, w10
  text ".Layer_Name" at 577,-858.49 h60
M2 Board Dimensions:
  rectangle: 0,-275 125,-150
  rectangle: 125,-400 500,-275
  lines w7: 0,-275 1000,-275 ; 125,-400 125,-150 ; 250,-400 250,-150 ; 500,-400 500,-150 ; 750,-400 750,-150 ; 0,-400 1000,-400 1000,-150 0,-150 0,-400
  text ".Layer_Name" at 577,-858.49 h60
M3 3D STEP Top:
  text ".Layer_Name" at 577,-858.49 h60
M4 3D STEP Bottom:
  text ".Layer_Name" at 577,-858.49 h60
M5 Assembly Top:
  lines w10: -292,-930.17 6308,-930.17 ; -292,-726.83 6310,-726.83 ; -292,-523.5 -292,-1133.5 3713,-1133.5 6310,-1133.5 6310,-523.5 -291.5,-523.5 -291.5,-1133.5 1284,-1133.5 ; 2173,-1133.5 2173,-523.5 ; 3440,-726.83 3440,-523.5 ; 4280,-726.83 4280,-523.5 ; 4902,-1140 4902,-937.17
  text "COMPONENTS MARKED 'DNP' SHOULD NOT BE POPULATED." at 1153.5,-318.5 h60
  text "ASSEMBLY VARIANT:" at 1153,-434 h60
  text ".VariantName" at 2189,-434 h60
  text "PCB VIEWED FROM TOP SIDE" at -228.5,-655.67 h60
  text "BOARD #:" at 2248,-655.67 h60
  text ".PRJ_Number" at 2793.5,-655.67 h60
  text "REV:" at 3638,-655.67 h60
  text ".PCB_Rev" at 3929.5,-655.67 h60
  text "SVN REV:" at 4476,-655.67 h60
  text ".VersionControl_RevNumber" at 4982,-655.67 h60
  text "TID #:" at 2248,-859 h60
  text ".TID" at 2793.5,-859 h60
  text "PLOT NAME =" at -228.5,-1064.34 h60
  text ".plot_File_Name" at 577,-1064.34 h60
  text "GENERATED    :" at 2250,-1064.34 h60
  text ".Print_Date" at 3119.5,-1064.34 h60
  text ".Print_Time" at 3848.5,-1064.34 h60
  text "TEXAS INSTRUMENTS" at 5113,-1064.34 h60
M6 Assembly Bottom:
  lines w10: -292.5,-727.33 6309.5,-727.33 ; -290.5,-930.67 6309.5,-930.67 ; 1115.5,-1140.5 1115.5,-937.67 ; 1737.5,-727.33 1737.5,-524 ; 2577.5,-727.33 2577.5,-524 ; 3844.5,-1134 3844.5,-524 ; 4733.5,-1134 6309,-1134 6309,-524 -292.5,-524 -292.5,-1134 2304.5,-1134 6309.5,-1134 6309.5,-524
  text "COMPONENTS MARKED 'DNP' SHOULD NOT BE POPULATED." at 6102,-318 h60
  text ".VariantName" at 5058,-434 h60
  text "ASSEMBLY VARIANT:" at 6097,-434 h60
  text ".VersionControl_RevNumber" at 1035.5,-656.17 h60
  text "SVN REV:" at 1541.5,-656.17 h60
  text ".PCB_Rev" at 2088,-656.17 h60
  text "REV:" at 2379.5,-656.17 h60
  text ".PRJ_Number" at 3224,-656.17 h60
  text "BOARD #:" at 3769.5,-656.17 h60
  text "PCB VIEWED FROM BOTTOM SIDE" at 6246,-656.17 h60
  text ".TID" at 3224,-859.5 h60
  text "TID #:" at 3769.5,-859.5 h60
  text "TEXAS INSTRUMENTS" at 904.5,-1064.84 h60
  text ".Print_Time" at 2169,-1064.84 h60
  text ".Print_Date" at 2898,-1064.84 h60
  text "GENERATED    :" at 3767.5,-1064.84 h60
  text ".plot_File_Name" at 5440.5,-1064.84 h60
  text "PLOT NAME =" at 6246,-1064.84 h60
M9 Title Sheet:
  drawing of 57 lines, arcs and shapes, not listed
  text "1" at 739.84,8036.5 h70
  text "2" at 3235.5,8036.5 h70
  text "3" at 5724.84,8036.5 h70
  text "4" at 8231.51,8036.5 h70
  text "5" at 10730.5,8036.5 h70
  text "6" at 13235.5,8036.5 h70
  text "A" at -416.5,6893.5 h70
  text "A" at 14383.5,6893.5 h70
  text "B" at -416.5,4513.5 h70
  text "B" at 14383.5,4513.5 h70
  text "C" at -416.5,2138.5 h70
  text "C" at 14383.5,2138.5 h70
  text "PROJECT TITLE:" at 11343.5,277.5 h45
  text ".PRJ_Title" at 11393.5,144.17 h70
  text "DESIGNED FOR:" at 11343.5,-23.5 h45
  text ".PRJ_Customer" at 11393.5,-163.5 h70
  text "D" at -416.5,-231.5 h70
  text "D" at 14383.5,-231.5 h70
  text "FILE NAME:" at 11343.5,-323.5 h45
  text ".PCB_File_Name_No_Path" at 11393.5,-443.5 h70
  text "Texas Instruments (TI) and/or its licensors do not warrant the accuracy or completeness of this specification" at 6374,-605.34 h45
  text "ENGINEER:" at 11343.5,-613.5 h45
  text "LAYOUT BY:" at 12848.5,-613.5 h45
  text "or any information contained therein. TI and/or its licensors do not warrant that this design will meet" at 6329.01,-718 h45
  text ".PRJ_Engineer" at 11393.5,-768.49 h70
  text ".PCB_Layout" at 12899,-768.49 h70
  text "the specifications, will be suitable for your application or fit for any particular purpose, or will operate in" at 6329.01,-830.67 h45
  text ".Layer_Name" at 577,-858.49 h60
  text "ALTIUM DESIGNER VERSION:" at 12848.5,-923.5 h45
  text "an implementation. TI and/or its licensors do not warrant that the design is production worthy. You should" at 6329.01,-943.33 h45
  text "completely validate and test your design implementation to confirm the system functionality for your application." at 6374,-1056 h45
  text ".print_Scale" at 11393.5,-1056.83 h70
  text ".Application_BuildNumber" at 12899,-1056.83 h70
  text "1" at 739.84,-1263.5 h70
  text "2" at 3235.5,-1263.5 h70
  text "3" at 5724.84,-1263.5 h70
  text "4" at 8231.51,-1263.5 h70
  text "5" at 10730.5,-1263.5 h70
  text "6" at 13235.5,-1263.5 h70
M10 Fab Notes:
  drawing of 189 lines, arcs and shapes, not listed
  text "DESIGN INFORMATION" at 12382.02,6356.17 h60
  text "MIN. TRACK WIDTH:" at 11737.46,6224.05 h60
  text "8" at 12833.7,6224.05 h60
  text "MIL" at 12988.46,6224.05 h60
  text "MIN. CLEARANCE:" at 11737.46,6099.92 h60
  text "0.2" at 12773.7,6099.93 h60
  text "mm" at 12988.46,6099.92 h60
  text "MIN. VIA PAD SIZE:" at 11737.46,5975.8 h60
  text "24" at 12803.71,5975.8 h60
  text "MIL" at 12988.46,5975.8 h60
  text "0.05mm (2MIL)" at 12432.46,5845.9 h60
  text "MINIMUM ANNULAR RING" at 11408.23,5837.67 h60
  text "EXTERNAL" at 13140.46,5837.67 h60
  text "PER" at 11608.23,5727.55 h60
  text "IPC-D-275 CLASS 2 LEVEL C" at 11828.23,5727.54 h60
  text "MIL, HOLES" at 13316.46,5627.07 h60
  text "+/-" at 12924,5618.48 h60
  text "+/-" at 13778,5618.48 h60
  text "REGISTRATION TOLERANCES:" at 11408.23,5617.42 h60
  text "METAL" at 12608,5617.42 h60
  text "5" at 13184.2,5617.42 h60
  text "3" at 14017.2,5617.42 h60
  text "MIL" at 14133.46,5617.42 h60
  text "HOLE SIZE TOLERANCE (UNLESS OTHERWISE SPECIFIED):" at 11408.23,5519.1 h60
  text "+/-" at 13778,5516.23 h60
  text "3" at 14017.2,5515.17 h60
  text "MIL" at 14133.46,5515.17 h60
  text "MATERIAL:" at 11333.46,5377.52 h60
  text "FR-4 High Tg" at 12319.9,5249 h60
  text "X" at 12175.46,5241.01 h60
  text "FR-408" at 11754.46,5236.49 h60
  text "OTHER" at 13242.46,5236.49 h60
  text "62 MIL (1.6mm) +/-10%" at 12074.56,5093.46 h60
  text "X" at 11954.46,5091.01 h60
  text "THICKNESS:" at 11408.23,5085.24 h60
  text "OTHER" at 13359.46,5085.24 h60
  text "TOLERANCE:" at 11408.23,4946.92 h60
  text "X" at 12256.46,4946.92 h60
  text "ANSI IPC-6012 TYPE 3 CLASS 2" at 12434.48,4946.92 h60
  text "OTHER +/-" at 12434.46,4802.73 h60
  text "BOW & TWIST:" at 11408.23,4657.54 h60
  text "X" at 12256.46,4657.54 h60
  text "ANSI IPC-6012 TYPE 3 CLASS 2" at 12434.48,4657.54 h60
  text "OTHER +/-" at 12434.46,4510.85 h60
  text "DRILLING:" at 11333.46,4380.23 h60
  text "NC_DRILL FILES" at 13094.46,4275.04 h60
  text "REFERENCE:" at 11408.23,4271.1 h60
  text "X" at 12065.46,4271.01 h60
  text "AS SHOWN" at 12243.46,4271.1 h60
  text "X" at 12966.46,4271.1 h60
  text "OTHER" at 13392.46,4128.85 h60
  text "PTH COPPER THICKNESS:" at 11407.91,4125.32 h60
  text "X" at 12547.14,4125.32 h60
  text "20-30 um" at 12675.14,4125.32 h60
  text "BOARD FINISH:" at 11333.46,3977.73 h60
  text "SILKSCREEN:" at 11488.68,3867.6 h60
  text "X" at 12446.46,3867.6 h60
  text "TOP" at 12563.46,3867.6 h60
  text "X" at 12956.46,3867.6 h60
  text "BOTTOM" at 13074.46,3867.6 h60
  text "SILKSCREEN COLOR:" at 11488.68,3712.41 h60
  text "X" at 12445.46,3712.41 h60
  text "WHITE" at 12563.46,3712.41 h60
  text "OTHER" at 13074.46,3712.41 h60
  text "X" at 12576.46,3568.96 h60
  text "GREEN" at 12694.46,3568.96 h60
  text "OTHER" at 13312.46,3568.96 h60
  text "SOLDER RESIST COLOR:" at 11488.68,3562.1 h60
  text "X" at 12576.46,3414.71 h60
  text "MATTE" at 12694.46,3414.71 h60
  text "SEMI-GLOSS" at 13312,3414.07 h60
  text "IMMERSION GOLD (ENIG)" at 12394.46,3241.94 h60
  text "ENEPIG" at 13732,3234.72 h60
  text "SURFACE FINISH:" at 11333.46,3233.72 h60
  text "X" at 12216.46,3233.72 h60
  text "IMM. TIN/SILVER OR EQUIV" at 11663,3096.4 h60
  text "OTHER" at 13094.46,3092.47 h60
  text "ARRAY/PANEL:" at 11333.46,2937.09 h60
  text "CUT AND TRIM PER M1 BOARD OUTLINE" at 12394.46,2928.87 h60
  text "N.C. ROUTE" at 12394.46,2792.9 h60
  text "X" at 13082.46,2792.9 h60
  text "V. SCORE" at 13260.46,2792.9 h60
  text "CERTIFICATION:" at 11333.46,2663.77 h60
  text "MATERIALS AND WORKMANSHIP FOR ALL PCBS" at 12058.46,2663.77 h60
  text "TO MEET OR EXCEED THE REQUIREMENTS OF:" at 12058.46,2569.71 h60
  text "X" at 11695.97,2441.08 h60
  text "ANSI IPC-A-600F CLASS ->" at 11823.96,2441.08 h60
  text "X" at 13471.97,2441.08 h60
  text "2" at 13581.96,2441.08 h60
  text "1" at 13266.96,2439.58 h60
  text "3" at 13935.96,2439.58 h60
  text "X" at 12507.97,2293.39 h60
  text "RoHS" at 12635.96,2293.39 h60
  text "OTHER" at 13280.36,2293.39 h60
  text "PER ORDER" at 13677.42,2293.39 h60
  text "ALL BOARDS MUST MEET OR EXCEED UL94-V0 REQUIREMENTS." at 11361,2139.57 h60
  text "PCB MUST BEAR THE UL94V-0 UL REGISTERED MATERIAL ID NUMBER" at 11361,2023.5 h60
  text "ADDITIONAL REQUIREMENTS:" at 11333.46,1854.08 h60
  text "MICROSECTION:" at 11408.23,1746.95 h60
  text "YES" at 12313.96,1746.95 h60
  text "REQUIRED" at 13175.46,1602.62 h60
  text "BARE BOARD ELEC. TEST:" at 11408.23,1599.76 h60
  text "NONE" at 12713.96,1599.76 h60
  text "X" at 13057.46,1599.76 h60
  text "PER ORDER" at 13767.46,1599.76 h60
  text "XX MIL VIAS REQUIRE NON-CONDUCTIVE FILL AND PLANARIZE" at 11576.38,1394.82 h59
  text "XX MIL VIAS REQUIRE CONDUCTIVE FILL AND PLANARIZE" at 11584.38,1290.84 h60
  text "OUTER XX MIL TRACES REQUIRE 50 OHM SINGLE-ENDED IMPEDANCE" at 11583.39,1127.46 h58
  text "LAYER 2 & 3 (INNER LAYERS) XX MIL WIDE, XX MIL SPACE / TRACES REQUIRE 100 OHM DIFFERENTIAL IMPEDANCE" at 11575.39,891.74 h60
  text ".Layer_Name" at 577,-858.49 h60
M11 Gerber Information:
  lines w10: -292,-930.17 6308,-930.17 ; -292,-726.83 6310,-726.83 ; -292,-523.5 -292,-1133.5 3713,-1133.5 6310,-1133.5 6310,-523.5 -291.5,-523.5 -291.5,-1133.5 1284,-1133.5 ; 2173,-1133.5 2173,-523.5 ; 3440,-726.83 3440,-523.5 ; 4280,-726.83 4280,-523.5 ; 4902,-1140 4902,-937.17
  text "ALL ARTWORK VIEWED FROM TOP SIDE" at -228.5,-655.67 h60
  text "BOARD #:" at 2248,-655.67 h60
  text ".PRJ_Number" at 2793.5,-655.67 h60
  text "REV:" at 3638,-655.67 h60
  text ".PCB_Rev" at 3929.5,-655.67 h60
  text "SVN REV:" at 4476,-655.67 h60
  text ".VersionControl_RevNumber" at 4982,-655.67 h60
  text "LAYER NAME =" at -228.5,-858.49 h60
  text "TID #:" at 2248,-859 h60
  text ".TID" at 2793.5,-859 h60
  text "PLOT NAME =" at -228.5,-1064.34 h60
  text ".plot_File_Name" at 577,-1064.34 h60
  text "GENERATED    :" at 2250,-1064.34 h60
  text ".Print_Date" at 3119.5,-1064.34 h60
  text ".Print_Time" at 3848.5,-1064.34 h60
  text "TEXAS INSTRUMENTS" at 5113,-1064.34 h60
M12 Stackup:
  text ".Layer_Name" at 577,-858.49 h60
M13 Component Bodies Top:
  text ".Layer_Name" at 577,-858.49 h60
M14 Component Bodies Bottom:
  text ".Layer_Name" at 577,-858.49 h60
M15 Courtyards Top:
  text ".Layer_Name" at 577,-858.49 h60
M16 Courtyards Bottom:
  text ".Layer_Name" at 577,-858.49 h60
Drill Drawing:
  text ".Layer_Name" at 577,-858.49 h60
M17 Embedded Cavity:
  text ".Layer_Name" at 577,-858.49 h60
M18 Embedded Assembly:
  text ".Layer_Name" at 577,-858.49 h60
M19 Embedded Keepout:
  text ".Layer_Name" at 577,-858.49 h60

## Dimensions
0,-400 to 1000,-400 on M2 Board Dimensions
0,0 to 0,4035 on M2 Board Dimensions
0,0 to 4600,0 on M2 Board Dimensions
